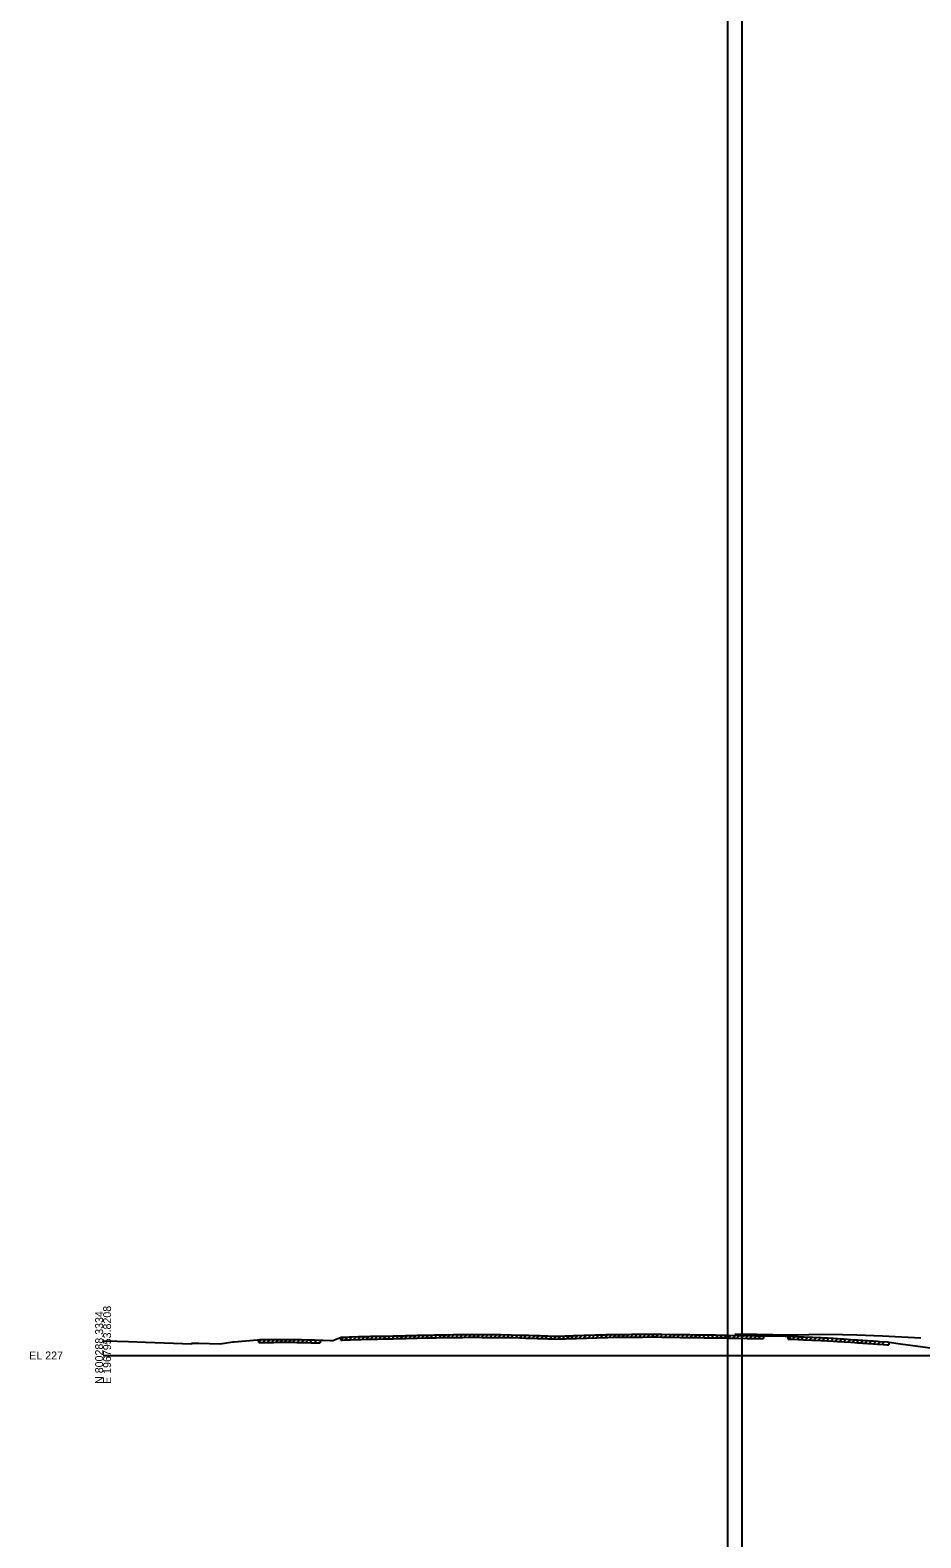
# Model space of a CAD drawing. Extents: x -119 to 6018, y -82 to 34226.
# Drawn here: x -26 to 288, y 30436 to 30967 of the extents above; entities that cross this region are included whole.
import ezdxf

# ---------------------------------------------------------------- set-up
doc = ezdxf.new("R2010")
doc.units = 0
for name, color, linetype in [('Default', 7, 'Continuous'), ('RD_GPK_XS_Cell', 7, 'Continuous'), ('RD_Sketch1', 7, 'Continuous'), ('RD_XS_ExGround', 7, 'Continuous'), ('RD_XS_ExPaveRet', 7, 'Continuous'), ('RD_XS_Pave', 7, 'Continuous')]:
    doc.layers.add(name, color=color, linetype=linetype)

msp = doc.modelspace()

# ---------------------------------------------------------------- linework, layer by layer
at = {"layer": 'RD_GPK_XS_Cell'}
msp.add_line((0, 30500), (300, 30500), dxfattribs=at)
at = {"layer": 'RD_Sketch1'}
for p, q in [((220, -82), (220, 34226.15)), ((225, -82), (225, 34226.15))]:
    msp.add_line(p, q, dxfattribs=at)
at = {"layer": 'RD_XS_ExGround'}
msp.add_lwpolyline([(0, 30505.21), (4.94, 30505.01), (8.99, 30504.9), (14.88, 30504.74), (21.51, 30504.47), (31.28, 30504.09), (31.38, 30504.39), (33.72, 30504.32), (41.21, 30504.12), (45.67, 30504.76), (46.14, 30504.8), (54.4, 30505.55), (55.05, 30505.58), (55.45, 30505.59), (56.83, 30505.6), (58.51, 30505.61), (59.98, 30505.63), (60.71, 30505.64), (62.03, 30505.64), (63.3, 30505.65), (64.49, 30505.66), (65.1, 30505.66), (66.03, 30505.66), (66.5, 30505.66), (68.21, 30505.63), (69.91, 30505.59), (71.91, 30505.55), (73.24, 30505.51), (74.43, 30505.48), (75.73, 30505.44), (76.42, 30505.41), (77.13, 30505.39), (77.46, 30505.38), (80.01, 30505.3), (80.92, 30505.27), (83.85, 30506.43), (84.18, 30506.45), (85.5, 30506.47), (86.76, 30506.55), (87.11, 30506.56), (89.95, 30506.64), (90.36, 30506.65), (90.87, 30506.66), (93.27, 30506.73), (94.17, 30506.75), (94.99, 30506.77), (96.6, 30506.8), (98.51, 30506.83), (99.95, 30506.86), (102.1, 30506.9), (103.28, 30506.93), (104.54, 30506.96), (106.13, 30506.98), (106.64, 30506.99), (109.92, 30507.08), (110.64, 30507.1), (113.46, 30507.17), (115.19, 30507.21), (116.56, 30507.24), (117.24, 30507.25), (118.67, 30507.28), (119.9, 30507.3), (121.13, 30507.31), (123.26, 30507.34), (123.98, 30507.35), (124.85, 30507.37), (125.79, 30507.38), (126.66, 30507.39), (128.58, 30507.42), (129.95, 30507.42), (131.12, 30507.41), (132.53, 30507.4), (133.34, 30507.39), (134.6, 30507.38), (136.63, 30507.36), (139.6, 30507.35), (140, 30507.35), (143.69, 30507.28), (146.63, 30507.2), (146.97, 30507.19), (147.47, 30507.17), (148.88, 30507.14), (149.88, 30507.11), (151.27, 30507.08), (152.86, 30507.04), (153.52, 30507.03), (153.87, 30507.01), (155.18, 30506.96), (155.86, 30506.94), (156.59, 30506.91), (158.74, 30506.83), (159.23, 30506.81), (159.81, 30506.79), (160.76, 30506.83), (162.67, 30506.91), (163.44, 30506.94), (164.7, 30506.95), (165.26, 30506.98), (165.68, 30506.99), (166.05, 30507.02), (166.67, 30507.03), (169.23, 30507.11), (170.29, 30507.14), (173.28, 30507.23), (173.65, 30507.24), (174, 30507.25), (176.61, 30507.33), (177.18, 30507.34), (177.71, 30507.36), (179.92, 30507.41), (180.69, 30507.42), (181.48, 30507.42), (183.22, 30507.44), (184.19, 30507.45), (185.41, 30507.45), (186.1, 30507.46), (186.6, 30507.46), (189.14, 30507.49), (189.58, 30507.49), (189.94, 30507.5), (192.88, 30507.53), (193.3, 30507.53), (194.88, 30507.54), (196.77, 30507.5), (199.96, 30507.45), (200.45, 30507.44), (203.29, 30507.39), (203.65, 30507.39), (204.11, 30507.38), (205.51, 30507.36), (206.63, 30507.34), (208.09, 30507.32), (209.94, 30507.29), (211.68, 30507.27), (213.26, 30507.25), (214.32, 30507.24), (215.69, 30507.22), (216.36, 30507.21), (217.01, 30507.21), (219.38, 30507.17), (219.92, 30507.15), (223.23, 30507.07), (223.76, 30507.07), (226.82, 30507.02), (229.93, 30506.96), (230.26, 30506.96), (230.58, 30506.95), (232.17, 30506.94), (232.58, 30506.93), (240.18, 30506.79), (241.26, 30506.76), (242.76, 30506.72), (243.3, 30506.7), (244.8, 30506.64), (245.57, 30506.61), (245.9, 30506.6), (246.65, 30506.56), (249.58, 30506.43), (249.96, 30506.41), (252.73, 30506.28), (253.35, 30506.25), (255.07, 30506.16), (257.13, 30506.05), (258.63, 30505.97), (259.96, 30505.88), (260.91, 30505.82), (263.26, 30505.66), (264.68, 30505.56), (265.69, 30505.49), (266.59, 30505.43), (267.47, 30505.37), (268.47, 30505.3), (269.28, 30505.24), (269.96, 30505.2), (271.14, 30505.13), (272.67, 30505.02), (273.28, 30504.98), (276.03, 30504.78), (276.66, 30504.73), (276.75, 30504.71), (280.82, 30504.11), (293.92, 30502.31)], dxfattribs=at)
at = {"layer": 'RD_XS_ExPaveRet'}
for p, q in [((54.79, 30504.57), (55.81, 30505.59)), ((54.79, 30504.57), (54.79, 30505.57)), ((56.29, 30504.59), (57.3, 30505.6)), ((57.79, 30504.61), (58.8, 30505.62)), ((58.51, 30504.61), (59.98, 30504.63)), ((59.29, 30504.62), (60.3, 30505.63)), ((59.98, 30504.63), (60.71, 30504.64)), ((60.71, 30504.64), (62.03, 30504.64)), ((60.79, 30504.64), (61.79, 30505.64)), ((62.03, 30504.64), (63.3, 30504.65)), ((62.29, 30504.65), (63.29, 30505.65)), ((63.3, 30504.65), (64.49, 30504.66)), ((63.79, 30504.65), (64.79, 30505.66)), ((64.49, 30504.66), (65.1, 30504.66)), ((65.1, 30504.66), (66.03, 30504.66)), ((65.29, 30504.66), (66.29, 30505.66)), ((66.03, 30504.66), (66.5, 30504.66)), ((66.5, 30504.66), (68.21, 30504.63)), ((66.79, 30504.65), (67.77, 30505.63)), ((68.21, 30504.63), (69.91, 30504.59)), ((68.29, 30504.62), (69.27, 30505.6)), ((69.79, 30504.59), (70.77, 30505.57)), ((71.29, 30504.56), (72.27, 30505.54)), ((72.79, 30504.52), (73.76, 30505.5)), ((74.29, 30504.48), (75.26, 30505.45)), ((76.4, 30505.42), (76.4, 30504.42)), ((83.65, 30505.35), (84.75, 30506.45)), ((83.65, 30505.35), (83.65, 30506.35)), ((83.65, 30505.35), (83.85, 30505.43)), ((83.85, 30505.43), (84.18, 30505.45)), ((84.18, 30505.45), (85.5, 30505.47)), ((85.15, 30505.46), (86.2, 30506.51)), ((85.5, 30505.47), (86.76, 30505.55)), ((86.65, 30505.54), (87.68, 30506.58)), ((86.76, 30505.55), (87.11, 30505.56)), ((87.11, 30505.56), (89.95, 30505.64)), ((88.15, 30505.59), (89.18, 30506.62)), ((89.65, 30505.63), (90.68, 30506.66)), ((89.95, 30505.64), (90.36, 30505.65)), ((90.36, 30505.65), (90.87, 30505.66)), ((90.87, 30505.66), (93.27, 30505.73)), ((91.15, 30505.67), (92.18, 30506.7)), ((92.65, 30505.71), (93.68, 30506.74)), ((93.27, 30505.73), (94.17, 30505.75)), ((94.15, 30505.75), (95.17, 30506.77)), ((94.17, 30505.75), (94.99, 30505.77)), ((94.99, 30505.77), (96.6, 30505.8)), ((95.65, 30505.78), (96.67, 30506.8)), ((96.6, 30505.8), (98.51, 30505.83)), ((97.15, 30505.81), (98.17, 30506.82)), ((98.51, 30505.83), (99.95, 30505.86)), ((98.65, 30505.83), (99.67, 30506.85)), ((99.95, 30505.86), (102.1, 30505.9)), ((100.15, 30505.86), (101.17, 30506.88)), ((101.65, 30505.89), (102.67, 30506.92)), ((102.1, 30505.9), (103.28, 30505.93)), ((103.15, 30505.93), (104.17, 30506.95)), ((103.28, 30505.93), (104.54, 30505.96)), ((104.54, 30505.96), (106.13, 30505.98)), ((104.65, 30505.96), (105.67, 30506.98)), ((106.13, 30505.98), (106.64, 30505.99)), ((106.15, 30505.98), (107.17, 30507.01)), ((106.64, 30505.99), (109.92, 30506.08)), ((107.65, 30506.02), (108.68, 30507.04)), ((109.15, 30506.06), (110.18, 30507.08)), ((109.92, 30506.08), (110.64, 30506.1)), ((110.64, 30506.1), (113.46, 30506.17)), ((110.65, 30506.1), (111.68, 30507.12)), ((112.15, 30506.14), (113.18, 30507.17)), ((113.46, 30506.17), (115.19, 30506.21)), ((113.65, 30506.18), (114.67, 30507.2)), ((115.15, 30506.21), (116.17, 30507.23)), ((115.19, 30506.21), (116.56, 30506.24)), ((116.56, 30506.24), (117.24, 30506.25)), ((116.65, 30506.24), (117.67, 30507.26)), ((117.24, 30506.25), (118.67, 30506.28)), ((118.15, 30506.27), (119.17, 30507.29)), ((118.67, 30506.28), (119.9, 30506.3)), ((119.65, 30506.29), (120.66, 30507.31)), ((119.9, 30506.3), (121.13, 30506.31)), ((121.13, 30506.31), (123.26, 30506.34)), ((121.15, 30506.31), (122.17, 30507.33)), ((122.65, 30506.33), (123.67, 30507.35)), ((123.26, 30506.34), (123.98, 30506.35)), ((123.98, 30506.35), (124.85, 30506.37)), ((124.15, 30506.36), (125.17, 30507.37)), ((124.85, 30506.37), (125.79, 30506.38)), ((125.65, 30506.38), (126.67, 30507.39)), ((125.79, 30506.38), (126.66, 30506.39)), ((126.66, 30506.39), (128.58, 30506.42)), ((127.15, 30506.4), (128.16, 30507.42)), ((128.58, 30506.42), (129.95, 30506.42)), ((128.65, 30506.42), (129.65, 30507.42)), ((129.95, 30506.42), (131.12, 30506.41)), ((130.15, 30506.42), (131.14, 30507.41)), ((131.12, 30506.41), (132.53, 30506.4)), ((131.65, 30506.41), (132.64, 30507.4)), ((132.53, 30506.4), (133.34, 30506.39)), ((133.15, 30506.39), (134.14, 30507.38)), ((133.34, 30506.39), (134.6, 30506.38)), ((134.6, 30506.38), (136.63, 30506.36)), ((134.65, 30506.38), (135.64, 30507.37)), ((136.15, 30506.37), (137.14, 30507.36)), ((136.63, 30506.36), (139.6, 30506.35)), ((137.65, 30506.36), (138.65, 30507.35)), ((139.15, 30506.35), (140.14, 30507.34)), ((139.6, 30506.35), (140, 30506.35)), ((140, 30506.35), (143.69, 30506.28)), ((140.65, 30506.33), (141.63, 30507.32)), ((142.15, 30506.31), (143.13, 30507.29)), ((143.65, 30506.28), (144.62, 30507.25)), ((143.69, 30506.28), (146.63, 30506.2)), ((145.15, 30506.24), (146.12, 30507.21)), ((146.63, 30506.2), (146.97, 30506.19)), ((146.65, 30506.2), (147.63, 30507.17)), ((146.97, 30506.19), (147.47, 30506.17)), ((147.47, 30506.17), (148.88, 30506.14)), ((148.15, 30506.16), (149.13, 30507.13)), ((148.88, 30506.14), (149.88, 30506.11)), ((149.65, 30506.12), (150.63, 30507.1)), ((149.88, 30506.11), (151.27, 30506.08)), ((151.15, 30506.08), (152.13, 30507.06)), ((151.27, 30506.08), (152.86, 30506.04)), ((152.65, 30506.05), (153.63, 30507.02)), ((152.86, 30506.04), (153.52, 30506.03)), ((153.52, 30506.03), (153.87, 30506.01)), ((153.87, 30506.01), (155.18, 30505.96)), ((154.15, 30506), (155.11, 30506.97)), ((155.18, 30505.96), (155.86, 30505.94)), ((155.65, 30505.95), (156.61, 30506.91)), ((155.86, 30505.94), (156.59, 30505.91)), ((156.59, 30505.91), (158.74, 30505.83)), ((157.15, 30505.89), (158.11, 30506.85)), ((158.65, 30505.83), (159.62, 30506.8)), ((158.74, 30505.83), (159.23, 30505.81)), ((159.23, 30505.81), (159.81, 30505.79)), ((159.81, 30505.79), (160.76, 30505.83)), ((160.15, 30505.81), (161.19, 30506.85)), ((160.76, 30505.83), (162.67, 30505.91)), ((161.65, 30505.87), (162.69, 30506.91)), ((162.67, 30505.91), (163.44, 30505.94)), ((163.15, 30505.93), (164.17, 30506.95)), ((163.44, 30505.94), (164.7, 30505.95)), ((164.65, 30505.95), (165.7, 30507)), ((164.7, 30505.95), (165.26, 30505.98)), ((165.26, 30505.98), (165.68, 30505.99)), ((165.68, 30505.99), (166.05, 30506.02)), ((166.05, 30506.02), (166.67, 30506.03)), ((166.15, 30506.02), (167.18, 30507.05)), ((166.67, 30506.03), (169.23, 30506.11)), ((167.65, 30506.06), (168.68, 30507.1)), ((169.15, 30506.11), (170.18, 30507.14)), ((169.23, 30506.11), (170.29, 30506.14)), ((170.29, 30506.14), (173.28, 30506.23)), ((170.65, 30506.15), (171.68, 30507.18)), ((172.15, 30506.2), (173.18, 30507.23)), ((173.28, 30506.23), (173.65, 30506.24)), ((173.65, 30506.24), (174.68, 30507.27)), ((173.65, 30506.24), (174, 30506.25)), ((174, 30506.25), (176.61, 30506.33)), ((175.15, 30506.28), (176.18, 30507.31)), ((176.61, 30506.33), (177.18, 30506.34)), ((176.65, 30506.33), (177.68, 30507.36)), ((177.18, 30506.34), (177.71, 30506.36)), ((177.71, 30506.36), (179.92, 30506.41)), ((178.15, 30506.37), (179.17, 30507.39)), ((179.65, 30506.4), (180.67, 30507.42)), ((179.92, 30506.41), (180.69, 30506.42)), ((180.69, 30506.42), (181.48, 30506.42)), ((181.15, 30506.42), (182.16, 30507.43)), ((181.48, 30506.42), (183.22, 30506.44)), ((182.65, 30506.43), (183.66, 30507.44)), ((183.22, 30506.44), (184.19, 30506.45)), ((184.15, 30506.44), (185.16, 30507.45)), ((184.19, 30506.45), (185.41, 30506.45)), ((185.41, 30506.45), (186.1, 30506.46)), ((185.65, 30506.45), (186.66, 30507.46)), ((186.1, 30506.46), (186.6, 30506.46)), ((186.6, 30506.46), (189.14, 30506.49)), ((187.15, 30506.47), (188.16, 30507.48)), ((188.65, 30506.48), (189.66, 30507.49)), ((189.14, 30506.49), (189.58, 30506.49)), ((189.58, 30506.49), (189.94, 30506.5)), ((189.94, 30506.5), (192.88, 30506.53)), ((190.15, 30506.5), (191.16, 30507.51)), ((191.65, 30506.52), (192.66, 30507.53)), ((192.88, 30506.53), (193.3, 30506.53)), ((193.15, 30506.53), (194.15, 30507.53)), ((193.3, 30506.53), (194.88, 30506.54)), ((194.65, 30506.54), (195.64, 30507.52)), ((194.88, 30506.54), (196.77, 30506.5)), ((196.15, 30506.51), (197.13, 30507.5)), ((196.77, 30506.5), (199.96, 30506.45)), ((197.65, 30506.49), (198.63, 30507.47)), ((199.15, 30506.46), (200.13, 30507.45)), ((199.96, 30506.45), (200.45, 30506.44)), ((200.45, 30506.44), (203.29, 30506.39)), ((200.65, 30506.44), (201.63, 30507.42)), ((202.15, 30506.41), (203.13, 30507.4)), ((203.29, 30506.39), (203.65, 30506.39)), ((203.65, 30506.39), (204.64, 30507.37)), ((203.65, 30506.39), (204.11, 30506.38)), ((204.11, 30506.38), (205.51, 30506.36)), ((205.15, 30506.36), (206.14, 30507.35)), ((205.51, 30506.36), (206.63, 30506.34)), ((206.63, 30506.34), (208.09, 30506.32)), ((206.65, 30506.34), (207.64, 30507.33)), ((208.09, 30506.32), (209.94, 30506.29)), ((208.15, 30506.32), (209.13, 30507.31)), ((209.65, 30506.3), (210.64, 30507.28)), ((209.94, 30506.29), (211.68, 30506.27)), ((211.15, 30506.28), (212.14, 30507.26)), ((211.68, 30506.27), (213.26, 30506.25)), ((212.65, 30506.26), (213.64, 30507.25)), ((213.26, 30506.25), (214.32, 30506.24)), ((214.15, 30506.24), (215.14, 30507.23)), ((214.32, 30506.24), (215.69, 30506.22)), ((215.65, 30506.22), (216.64, 30507.21)), ((215.69, 30506.22), (216.36, 30506.21)), ((216.36, 30506.21), (217.01, 30506.21)), ((217.01, 30506.21), (219.38, 30506.17)), ((217.15, 30506.21), (218.13, 30507.19)), ((218.65, 30506.18), (219.63, 30507.16)), ((219.38, 30506.17), (219.92, 30506.15)), ((219.92, 30506.15), (223.23, 30506.07)), ((220.15, 30506.15), (221.13, 30507.12)), ((221.65, 30506.11), (222.63, 30507.09)), ((223.15, 30506.08), (224.13, 30507.06)), ((223.23, 30506.07), (223.76, 30506.07)), ((223.76, 30506.07), (226.82, 30506.02)), ((224.65, 30506.05), (225.64, 30507.04)), ((226.15, 30506.03), (227.13, 30507.01)), ((226.82, 30506.02), (229.93, 30505.96)), ((227.65, 30506), (228.63, 30506.99)), ((229.15, 30505.98), (230.13, 30506.96)), ((229.93, 30505.96), (230.26, 30505.96)), ((230.26, 30505.96), (230.58, 30505.95)), ((230.58, 30505.95), (232.17, 30505.94)), ((230.65, 30505.95), (231.64, 30506.94)), ((232.17, 30505.94), (232.58, 30505.93)), ((232.58, 30506.93), (232.58, 30505.93)), ((241.26, 30505.76), (241.26, 30506.76)), ((241.26, 30505.76), (242.23, 30506.73)), ((241.26, 30505.76), (242.76, 30505.72)), ((242.76, 30505.72), (243.73, 30506.68)), ((242.76, 30505.72), (243.3, 30505.7)), ((243.3, 30505.7), (244.8, 30505.64)), ((244.26, 30505.66), (245.23, 30506.62)), ((244.8, 30505.64), (245.57, 30505.61)), ((245.57, 30505.61), (245.9, 30505.6)), ((245.76, 30505.6), (246.72, 30506.56)), ((245.9, 30505.6), (246.65, 30505.56)), ((246.65, 30505.56), (249.58, 30505.43)), ((247.26, 30505.54), (248.22, 30506.49)), ((248.76, 30505.47), (249.72, 30506.42)), ((249.58, 30505.43), (249.96, 30505.41)), ((249.96, 30505.41), (252.73, 30505.28)), ((250.26, 30505.4), (251.22, 30506.35)), ((251.76, 30505.32), (252.72, 30506.28)), ((252.73, 30505.28), (253.35, 30505.25)), ((253.26, 30505.25), (254.22, 30506.21)), ((253.35, 30505.25), (255.07, 30505.16)), ((254.76, 30505.18), (255.71, 30506.13)), ((255.07, 30505.16), (257.13, 30505.05)), ((256.26, 30505.1), (257.21, 30506.05)), ((257.13, 30505.05), (258.63, 30504.97)), ((257.76, 30505.02), (258.71, 30505.96)), ((258.63, 30504.97), (259.96, 30504.88)), ((259.26, 30504.93), (260.2, 30505.86)), ((259.96, 30504.88), (260.91, 30504.82)), ((260.76, 30504.83), (261.7, 30505.77)), ((260.91, 30504.82), (263.26, 30504.66)), ((262.26, 30504.73), (263.2, 30505.67)), ((263.26, 30504.66), (264.68, 30504.56)), ((263.76, 30504.63), (264.7, 30505.56)), ((265.26, 30504.52), (266.2, 30505.46)), ((266.76, 30504.42), (267.7, 30505.35)), ((268.26, 30504.32), (269.2, 30505.25)), ((269.76, 30504.21), (270.7, 30505.15)), ((271.26, 30504.12), (272.2, 30505.05)), ((272.76, 30504.01), (273.7, 30504.95)), ((274.26, 30503.91), (275.2, 30504.84)), ((276.66, 30504.73), (276.66, 30503.73)), ((54.79, 30504.57), (55.05, 30504.58)), ((55.05, 30504.58), (55.45, 30504.59)), ((55.45, 30504.59), (56.83, 30504.6)), ((56.83, 30504.6), (58.51, 30504.61)), ((69.91, 30504.59), (71.91, 30504.55)), ((71.91, 30504.55), (73.24, 30504.51)), ((73.24, 30504.51), (74.43, 30504.48)), ((74.43, 30504.48), (75.73, 30504.44)), ((75.73, 30504.44), (76.4, 30504.42)), ((264.68, 30504.56), (265.69, 30504.49)), ((265.69, 30504.49), (266.59, 30504.43)), ((266.59, 30504.43), (267.47, 30504.37)), ((267.47, 30504.37), (268.47, 30504.3)), ((268.47, 30504.3), (269.28, 30504.24)), ((269.28, 30504.24), (269.96, 30504.2)), ((269.96, 30504.2), (271.14, 30504.13)), ((271.14, 30504.13), (272.67, 30504.02)), ((272.67, 30504.02), (273.28, 30503.98)), ((273.28, 30503.98), (276.03, 30503.78)), ((276.03, 30503.78), (276.66, 30503.73))]:
    msp.add_line(p, q, dxfattribs=at)
at = {"layer": 'RD_XS_Pave'}
msp.add_lwpolyline([(222.49, 30507.63), (230.28, 30507.52), (241.33, 30507.29), (248.51, 30507.44), (253.35, 30507.55), (260.37, 30507.42), (265.37, 30507.33), (274.44, 30506.9), (287.94, 30506.22)], dxfattribs=at)

# ---------------------------------------------------------------- texts
at = {"layer": 'Default'}
msp.add_text('-', height=0.0001, dxfattribs=at).set_placement((0, 30500))
at = {"layer": 'RD_GPK_XS_Cell'}
for s, p in [('N 800288.3334', (0, 30490)), ('E 1967953.8208', (2.8, 30490))]:
    msp.add_text(s, height=2.8, rotation=90, dxfattribs=at).set_placement(p)
msp.add_text('EL 227', height=2.8, dxfattribs=at).set_placement((-26, 30498.6))

doc.saveas('drawing.dxf')
